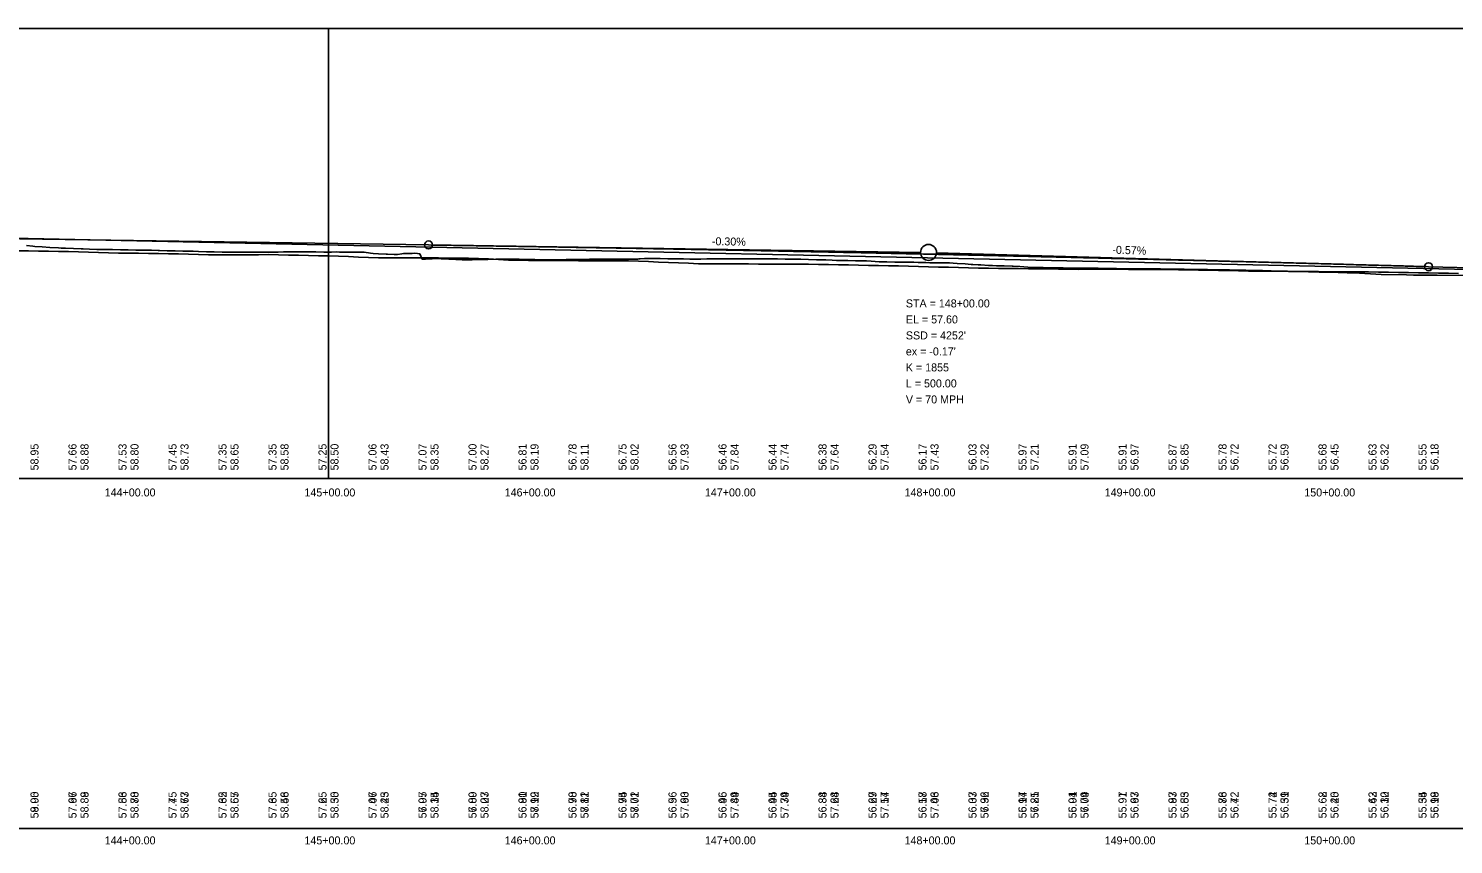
# Model space of a CAD drawing. Extents: x 3880794 to 3915434, y 287517 to 300173.
# Drawn here: x 3894888 to 3895601, y 297716 to 298124 of the extents above; entities that cross this region are included whole.
import ezdxf

# ---------------------------------------------------------------- set-up
doc = ezdxf.new("R2010")
doc.units = 0
for name, color, linetype in [('Level 1', 7, 'Continuous'), ('Level 2', 7, 'Continuous'), ('Level 30', 7, 'Continuous'), ('Level 31', 7, 'Continuous'), ('Level 32', 7, 'Continuous'), ('Level 62', 7, 'Continuous'), ('Level 63', 7, 'Continuous')]:
    doc.layers.add(name, color=color, linetype=linetype)

msp = doc.modelspace()

# ---------------------------------------------------------------- linework, layer by layer
at = {"layer": 'Level 1'}
for p, q in [((3894788.3, 298020.44), (3895088.3, 298015.94)), ((3895088.3, 298015.94), (3895334.3, 298012.25)), ((3895588.3, 298005.07), (3895342.3, 298012.08)), ((3895588.3, 298005.07), (3895939.87, 297995.06))]:
    msp.add_line(p, q, dxfattribs=at)
for points in [[(3894887.29, 298015.6), (3894890.4, 298015.3), (3894891.45, 298015.23), (3894895.11, 298014.97), (3894899.02, 298014.71), (3894903.22, 298014.44), (3894904.59, 298014.36), (3894906.85, 298014.26), (3894910.75, 298014.11), (3894914.67, 298013.98), (3894915.67, 298013.94), (3894918.85, 298013.79), (3894922.49, 298013.72), (3894926.4, 298013.66), (3894930.31, 298013.62), (3894934.23, 298013.59), (3894938.13, 298013.49), (3894942.04, 298013.41), (3894945.95, 298013.34), (3894948.52, 298013.31), (3894949.86, 298013.27), (3894953.14, 298013.2), (3894953.77, 298013.18), (3894957.69, 298013.07), (3894961.6, 298012.97), (3894965.51, 298012.89), (3894967.48, 298012.86), (3894969.42, 298012.8), (3894970.56, 298012.77), (3894973.33, 298012.67), (3894977.24, 298012.55), (3894981.15, 298012.44), (3894985.15, 298012.35), (3894988.97, 298012.31), (3894992.88, 298012.32), (3894996.79, 298012.35), (3895000.7, 298012.39), (3895004.62, 298012.38), (3895008.53, 298012.39), (3895012.44, 298012.41), (3895013.09, 298012.42), (3895015.82, 298012.46), (3895016.35, 298012.46), (3895020.26, 298012.45), (3895024.17, 298012.45), (3895028.08, 298012.47), (3895028.39, 298012.47), (3895029.75, 298012.46), (3895031.99, 298012.44), (3895035.9, 298012.42), (3895039.81, 298012.42), (3895042.29, 298012.43), (3895043.73, 298012.39), (3895047.63, 298012.35), (3895051.54, 298012.33), (3895055.46, 298012.33), (3895056.14, 298012.33), (3895059.37, 298011.85), (3895060.62, 298011.67), (3895063.28, 298011.57), (3895067.19, 298011.3), (3895067.85, 298011.26), (3895071.1, 298011.24), (3895072.76, 298011.23), (3895075.01, 298011.54), (3895075.77, 298011.64), (3895078.92, 298011.68), (3895080.16, 298011.69), (3895081.44, 298011.76), (3895082.83, 298011.61), (3895084.03, 298011.5), (3895085.11, 298008.85), (3895085.54, 298008.8), (3895086.06, 298008.85), (3895086.74, 298008.89), (3895088.52, 298008.97), (3895089.55, 298008.97)], [(3895089.55, 298008.97), (3895089.86, 298008.94), (3895090.18, 298009.03), (3895090.77, 298009.11), (3895094.56, 298008.95), (3895098.48, 298008.79), (3895102, 298008.65), (3895102.39, 298008.62), (3895105.06, 298008.48), (3895106.3, 298008.5), (3895110.21, 298008.58), (3895114.12, 298008.66), (3895118.03, 298008.74), (3895121.94, 298008.82), (3895124.48, 298008.86), (3895124.83, 298008.86), (3895125.85, 298008.88), (3895126.46, 298008.89), (3895127.21, 298008.88), (3895129.76, 298008.84), (3895133.67, 298008.78), (3895137.58, 298008.71), (3895141.49, 298008.64), (3895145.41, 298008.57), (3895149.31, 298008.5), (3895149.84, 298008.49), (3895150.46, 298008.52), (3895153.23, 298008.55), (3895157.14, 298008.61), (3895161.05, 298008.66), (3895164.96, 298008.71), (3895168.87, 298008.76), (3895170.82, 298008.77), (3895172.78, 298008.81), (3895174.14, 298008.84), (3895176.69, 298008.85), (3895180.6, 298008.85), (3895184.51, 298008.86), (3895188.42, 298008.87), (3895192.33, 298008.88), (3895192.96, 298008.88), (3895193.58, 298009.02), (3895194.16, 298009.04), (3895196.25, 298009.12), (3895198.15, 298009.2), (3895200.16, 298009.17), (3895204.07, 298009.12), (3895207.98, 298009.07), (3895211.89, 298009.02), (3895215.8, 298008.96), (3895219.02, 298008.91), (3895219.71, 298008.91), (3895223.62, 298008.92), (3895224.48, 298008.92), (3895227.53, 298008.93), (3895231.44, 298008.93), (3895235.35, 298008.93), (3895239.26, 298008.93), (3895242.09, 298008.93), (3895243.18, 298008.94), (3895247.09, 298008.97), (3895249.09, 298008.98), (3895251, 298008.98), (3895254.91, 298008.98), (3895258.82, 298008.98), (3895260.18, 298008.98), (3895262.73, 298008.95), (3895266.64, 298008.92), (3895269.11, 298008.9), (3895270.55, 298008.86), (3895274.46, 298008.77), (3895278.37, 298008.67), (3895282.28, 298008.57), (3895284.82, 298008.51), (3895286.19, 298008.47), (3895286.9, 298008.45), (3895290.1, 298008.3), (3895292.26, 298008.2), (3895294.02, 298008.18), (3895297.93, 298008.12), (3895301.84, 298008.07), (3895305.75, 298008.01), (3895307.28, 298007.99), (3895309.66, 298007.8), (3895313.57, 298007.5), (3895314.04, 298007.47), (3895314.57, 298007.46), (3895317.48, 298007.43), (3895321.39, 298007.39), (3895322.29, 298007.38), (3895325.3, 298007.35), (3895329.21, 298007.31), (3895330.96, 298007.29), (3895333.12, 298007.23), (3895337.04, 298007.11), (3895338.95, 298007.06), (3895340.01, 298007.02), (3895340.95, 298007.04), (3895341.51, 298007.05), (3895344.86, 298007), (3895348.77, 298006.94)], [(3895348.77, 298006.94), (3895350.58, 298006.91), (3895352.68, 298006.75), (3895356.59, 298006.45), (3895359.56, 298006.22), (3895360.5, 298006.17), (3895363.13, 298006.03), (3895364.41, 298005.96), (3895368.32, 298005.74), (3895370.36, 298005.63), (3895372.23, 298005.57), (3895376.19, 298005.44), (3895380.05, 298005.38), (3895380.63, 298005.38), (3895383.96, 298005.16), (3895387.88, 298004.92), (3895391.79, 298004.67), (3895392.42, 298004.63), (3895395.7, 298004.59), (3895399.61, 298004.53), (3895403.52, 298004.48), (3895405.56, 298004.45), (3895407.43, 298004.42), (3895411.34, 298004.39), (3895415.25, 298004.36), (3895419.45, 298004.33), (3895423.07, 298004.27), (3895426.98, 298004.2), (3895430.89, 298004.13), (3895431.87, 298004.11), (3895432.24, 298004.11), (3895434.81, 298004.07), (3895435.86, 298004.05), (3895438.72, 298004.05), (3895442.63, 298004.04), (3895446.54, 298004.03), (3895449.77, 298004.02), (3895450.45, 298004.02), (3895450.97, 298004.02), (3895454.36, 298003.97), (3895458.27, 298003.91), (3895460.23, 298003.88), (3895462.18, 298003.85), (3895466.09, 298003.8), (3895470, 298003.75), (3895473.91, 298003.7), (3895476.71, 298003.67), (3895477.82, 298003.65), (3895484.82, 298003.54), (3895486.85, 298003.52), (3895488.82, 298003.46), (3895505.33, 298003.09), (3895514.12, 298002.86), (3895517.76, 298002.78), (3895533.56, 298002.39), (3895543.07, 298002.15), (3895547.55, 298002.04), (3895551.18, 298001.98), (3895564.66, 298001.21), (3895577.36, 298001.05), (3895580.87, 298000.88), (3895592.62, 298000.86), (3895605.89, 298000.7)]]:
    msp.add_lwpolyline(points, dxfattribs=at)
msp.add_circle((3895338.3, 298012.19), 4, dxfattribs=at)
msp.add_spline([(3895088.3, 298015.94), (3895098.3, 298015.79), (3895108.3, 298015.64), (3895118.3, 298015.48), (3895128.3, 298015.32), (3895138.3, 298015.16), (3895148.3, 298014.99), (3895158.3, 298014.82), (3895168.3, 298014.65), (3895178.3, 298014.48), (3895188.3, 298014.31), (3895198.3, 298014.13), (3895208.3, 298013.95), (3895218.3, 298013.76), (3895228.3, 298013.58), (3895238.3, 298013.39), (3895248.3, 298013.2), (3895258.3, 298013), (3895268.3, 298012.8), (3895278.3, 298012.6), (3895288.3, 298012.4), (3895298.3, 298012.2), (3895308.3, 298011.99), (3895318.3, 298011.78), (3895328.3, 298011.56), (3895338.3, 298011.35), (3895348.3, 298011.13), (3895358.3, 298010.91), (3895368.3, 298010.68), (3895378.3, 298010.46), (3895388.3, 298010.23), (3895398.3, 298009.99), (3895408.3, 298009.76), (3895418.3, 298009.52), (3895428.3, 298009.28), (3895438.3, 298009.04), (3895448.3, 298008.79), (3895458.3, 298008.54), (3895468.3, 298008.29), (3895478.3, 298008.04), (3895488.3, 298007.78), (3895498.3, 298007.53), (3895508.3, 298007.26), (3895518.3, 298007), (3895528.3, 298006.73), (3895538.3, 298006.46), (3895548.3, 298006.19), (3895558.3, 298005.91), (3895568.3, 298005.64), (3895578.3, 298005.35), (3895588.3, 298005.07)], degree=3, dxfattribs=at)
at = {"layer": 'Level 2'}
msp.add_line((3894788.3, 298021.32), (3895938.3, 297996.62), dxfattribs=at)
for points in [[(3894883.3, 298013.04), (3894888.3, 298012.98), (3894893.3, 298012.91), (3894898.3, 298012.83), (3894903.3, 298012.74), (3894908.3, 298012.61), (3894913.3, 298012.49), (3894918.3, 298012.34), (3894923.3, 298012.18), (3894928.3, 298012.02), (3894933.3, 298011.89), (3894938.3, 298011.85), (3894943.3, 298011.78), (3894948.3, 298011.71), (3894953.3, 298011.63), (3894958.3, 298011.57), (3894963.3, 298011.46), (3894968.3, 298011.32), (3894973.3, 298011.17), (3894978.3, 298011.03), (3894983.3, 298010.99), (3894988.3, 298010.96), (3894993.3, 298011), (3894998.3, 298011.04), (3895003.3, 298011.08), (3895008.3, 298011.11), (3895013.3, 298010.96), (3895018.3, 298010.87), (3895023.3, 298010.78), (3895028.3, 298010.68), (3895033.3, 298010.59), (3895038.3, 298010.44)], [(3895038.3, 298010.44), (3895043.3, 298010.29), (3895048.3, 298010.1), (3895053.3, 298009.9), (3895058.3, 298009.7), (3895063.3, 298009.51), (3895068.3, 298009.46), (3895073.3, 298009.49), (3895078.3, 298009.52), (3895083.3, 298009.54), (3895088.3, 298009.52), (3895093.3, 298009.47), (3895098.3, 298009.4), (3895103.3, 298009.33), (3895108.3, 298009.26), (3895113.3, 298009.2), (3895118.3, 298008.94), (3895123.3, 298008.68), (3895128.3, 298008.42), (3895133.3, 298008.26), (3895138.3, 298008.23), (3895143.3, 298008.2), (3895148.3, 298008.15), (3895153.3, 298008.11), (3895158.3, 298008.1), (3895163.3, 298008.08), (3895168.3, 298008.05), (3895173.3, 298007.95), (3895178.3, 298007.95), (3895183.3, 298007.95), (3895188.3, 298007.96), (3895193.3, 298007.8), (3895198.3, 298007.59), (3895203.3, 298007.37), (3895208.3, 298007.16), (3895213.3, 298006.98), (3895218.3, 298006.84), (3895223.3, 298006.45), (3895228.3, 298006.45), (3895233.3, 298006.46), (3895238.3, 298006.47), (3895243.3, 298006.47), (3895248.3, 298006.46), (3895253.3, 298006.41), (3895258.3, 298006.41), (3895263.3, 298006.4), (3895268.3, 298006.39), (3895273.3, 298006.35), (3895278.3, 298006.27), (3895283.3, 298006.19), (3895288.3, 298006.1), (3895293.3, 298006.02), (3895298.3, 298005.95), (3895303.3, 298005.85), (3895308.3, 298005.75), (3895313.3, 298005.65), (3895318.3, 298005.52), (3895323.3, 298005.47), (3895328.3, 298005.33), (3895333.3, 298005.2), (3895338.3, 298005.06), (3895343.3, 298004.92), (3895348.3, 298004.77), (3895353.3, 298004.62), (3895358.3, 298004.47), (3895363.3, 298004.35), (3895368.3, 298004.3), (3895373.3, 298004.25), (3895378.3, 298004.2), (3895383.3, 298004.15), (3895388.3, 298004.05), (3895393.3, 298004), (3895398.3, 298003.93), (3895403.3, 298003.86), (3895408.3, 298003.79), (3895413.3, 298003.74), (3895418.3, 298003.77), (3895423.3, 298003.78), (3895428.3, 298003.8), (3895433.3, 298003.81), (3895438.3, 298003.73), (3895443.3, 298003.74), (3895448.3, 298003.75), (3895453.3, 298003.75), (3895458.3, 298003.61), (3895463.3, 298003.53), (3895468.3, 298003.44), (3895473.3, 298003.36), (3895478.3, 298003.27), (3895483.3, 298003.21), (3895488.3, 298003.11), (3895493.3, 298003.02), (3895498.3, 298002.92), (3895503.3, 298002.85), (3895508.3, 298002.82), (3895513.3, 298002.78), (3895518.3, 298002.74), (3895523.3, 298002.7), (3895528.3, 298002.66), (3895533.3, 298002.62), (3895538.3, 298002.58)], [(3895538.3, 298002.58), (3895543.3, 298002.54), (3895548.3, 298002.51), (3895553.3, 298002.47), (3895558.3, 298002.43), (3895563.3, 298002.35), (3895568.3, 298002.27), (3895573.3, 298002.19), (3895578.3, 298002.11), (3895583.3, 298002.02), (3895588.3, 298001.93), (3895593.3, 298001.85), (3895598.3, 298001.77), (3895603.3, 298001.69)]]:
    msp.add_lwpolyline(points, dxfattribs=at)
at = {"layer": 'Level 31'}
for centre in [(3895088.3, 298015.94), (3895588.3, 298005.07)]:
    msp.add_circle(centre, 2, dxfattribs=at)
at = {"layer": 'Level 62'}
for points in [[(3894338.3, 297899.19), (3895038.3, 297899.19), (3895038.3, 298124.19), (3894338.3, 298124.19)], [(3894338.3, 297899.19), (3895038.3, 297899.19), (3895038.3, 298124.19), (3894338.3, 298124.19)], [(3895038.3, 297899.19), (3895738.3, 297899.19), (3895738.3, 298124.19), (3895038.3, 298124.19)], [(3895038.3, 297899.19), (3895738.3, 297899.19), (3895738.3, 298124.19), (3895038.3, 298124.19)]]:
    msp.add_lwpolyline(points, close=True, dxfattribs=at)
at = {"layer": 'Level 63'}
msp.add_line((3881538.3, 297724.19), (3896411.35, 297724.19), dxfattribs=at)

# ---------------------------------------------------------------- texts
at = {"layer": 'Level 30'}
for s, p in [('144+00.00', (3894926.39, 297890.19)), ('144+00.00', (3894926.39, 297890.19)), ('145+00.00', (3895026.27, 297890.19)), ('145+00.00', (3895026.27, 297890.19)), ('146+00.00', (3895126.39, 297890.19)), ('146+00.00', (3895126.39, 297890.19)), ('147+00.00', (3895226.49, 297890.19)), ('147+00.00', (3895226.49, 297890.19)), ('148+00.00', (3895326.33, 297890.19)), ('148+00.00', (3895326.33, 297890.19)), ('149+00.00', (3895426.39, 297890.19)), ('149+00.00', (3895426.39, 297890.19)), ('150+00.00', (3895526.2, 297890.19)), ('150+00.00', (3895526.2, 297890.19)), ('144+00.00', (3894926.39, 297716.19)), ('144+00.00', (3894926.39, 297716.19)), ('145+00.00', (3895026.27, 297716.19)), ('145+00.00', (3895026.27, 297716.19)), ('146+00.00', (3895126.39, 297716.19)), ('146+00.00', (3895126.39, 297716.19)), ('147+00.00', (3895226.49, 297716.19)), ('147+00.00', (3895226.49, 297716.19)), ('148+00.00', (3895326.33, 297716.19)), ('148+00.00', (3895326.33, 297716.19)), ('149+00.00', (3895426.39, 297716.19)), ('149+00.00', (3895426.39, 297716.19)), ('150+00.00', (3895526.2, 297716.19)), ('150+00.00', (3895526.2, 297716.19))]:
    msp.add_text(s, height=4, dxfattribs=at).set_placement(p)
at = {"layer": 'Level 31'}
for s, rotation, p in [('-0.30%', 359.14063, (3895229.96, 298015.82)), ('-0.57%', 358.3687, (3895430.19, 298011.58)), ('58.95', 90, (3894893.3, 297903.19)), ('58.88', 90, (3894918.3, 297903.19)), ('58.80', 90, (3894943.3, 297903.19)), ('58.73', 90, (3894968.3, 297903.19)), ('58.65', 90, (3894993.3, 297903.19)), ('58.58', 90, (3895018.3, 297903.19)), ('58.50', 90, (3895043.3, 297903.19)), ('58.43', 90, (3895068.3, 297903.19)), ('58.35', 90, (3895093.3, 297903.19)), ('58.27', 90, (3895118.3, 297903.19)), ('58.19', 90, (3895143.3, 297903.19)), ('58.11', 90, (3895168.3, 297903.19)), ('58.02', 90, (3895193.3, 297903.19)), ('57.93', 90, (3895218.3, 297903.19)), ('57.84', 90, (3895243.3, 297903.19)), ('57.74', 90, (3895268.3, 297903.19)), ('57.64', 90, (3895293.3, 297903.19)), ('57.54', 90, (3895318.3, 297903.19)), ('57.43', 90, (3895343.3, 297903.19)), ('57.32', 90, (3895368.3, 297903.19)), ('57.21', 90, (3895393.3, 297903.19)), ('57.09', 90, (3895418.3, 297903.19)), ('56.97', 90, (3895443.3, 297903.19)), ('56.85', 90, (3895468.3, 297903.19)), ('56.72', 90, (3895493.3, 297903.19)), ('56.59', 90, (3895518.3, 297903.19)), ('56.45', 90, (3895543.3, 297903.19)), ('56.32', 90, (3895568.3, 297903.19)), ('56.18', 90, (3895593.3, 297903.19)), ('58.95', 90, (3894893.3, 297729.19)), ('57.97', 90, (3894912.3, 297729.19)), ('58.88', 90, (3894918.3, 297729.19)), ('57.86', 90, (3894937.3, 297729.19)), ('58.80', 90, (3894943.3, 297729.19)), ('57.75', 90, (3894962.3, 297729.19)), ('58.73', 90, (3894968.3, 297729.19)), ('57.62', 90, (3894987.3, 297729.19)), ('58.65', 90, (3894993.3, 297729.19)), ('57.65', 90, (3895012.3, 297729.19)), ('58.58', 90, (3895018.3, 297729.19)), ('57.65', 90, (3895037.3, 297729.19)), ('58.50', 90, (3895043.3, 297729.19)), ('57.47', 90, (3895062.3, 297729.19)), ('58.43', 90, (3895068.3, 297729.19)), ('56.95', 90, (3895087.3, 297729.19)), ('58.35', 90, (3895093.3, 297729.19)), ('56.89', 90, (3895112.3, 297729.19)), ('58.27', 90, (3895118.3, 297729.19)), ('56.90', 90, (3895137.3, 297729.19)), ('58.19', 90, (3895143.3, 297729.19)), ('56.90', 90, (3895162.3, 297729.19)), ('58.11', 90, (3895168.3, 297729.19)), ('56.94', 90, (3895187.3, 297729.19)), ('58.02', 90, (3895193.3, 297729.19)), ('56.96', 90, (3895212.3, 297729.19)), ('57.93', 90, (3895218.3, 297729.19)), ('56.95', 90, (3895237.3, 297729.19)), ('57.84', 90, (3895243.3, 297729.19)), ('56.95', 90, (3895262.3, 297729.19)), ('57.74', 90, (3895268.3, 297729.19)), ('56.84', 90, (3895287.3, 297729.19)), ('57.64', 90, (3895293.3, 297729.19)), ('56.67', 90, (3895312.3, 297729.19)), ('57.54', 90, (3895318.3, 297729.19)), ('56.58', 90, (3895337.3, 297729.19)), ('57.43', 90, (3895343.3, 297729.19)), ('56.37', 90, (3895362.3, 297729.19)), ('57.32', 90, (3895368.3, 297729.19)), ('56.14', 90, (3895387.3, 297729.19)), ('57.21', 90, (3895393.3, 297729.19)), ('56.04', 90, (3895412.3, 297729.19)), ('57.09', 90, (3895418.3, 297729.19)), ('55.97', 90, (3895437.3, 297729.19)), ('56.97', 90, (3895443.3, 297729.19)), ('55.93', 90, (3895462.3, 297729.19)), ('56.85', 90, (3895468.3, 297729.19)), ('55.86', 90, (3895487.3, 297729.19)), ('56.72', 90, (3895493.3, 297729.19)), ('55.74', 90, (3895512.3, 297729.19)), ('56.59', 90, (3895518.3, 297729.19)), ('55.62', 90, (3895537.3, 297729.19)), ('56.45', 90, (3895543.3, 297729.19)), ('55.42', 90, (3895562.3, 297729.19)), ('56.32', 90, (3895568.3, 297729.19)), ('55.34', 90, (3895587.3, 297729.19)), ('56.18', 90, (3895593.3, 297729.19))]:
    msp.add_text(s, height=4, rotation=rotation, dxfattribs=at).set_placement(p)
for s, p in [('STA = 148+00.00', (3895326.98, 297984.71)), ('EL = 57.60', (3895326.98, 297976.71)), ("SSD = 4252'", (3895326.98, 297968.71)), ("ex = -0.17'", (3895326.98, 297960.71)), ('K = 1855', (3895326.98, 297952.71)), ('L = 500.00', (3895326.98, 297944.71)), ('V = 70 MPH', (3895326.98, 297936.71))]:
    msp.add_text(s, height=4, dxfattribs=at).set_placement(p)
at = {"layer": 'Level 32'}
for s, p in [('57.66', (3894912.3, 297903.19)), ('57.53', (3894937.3, 297903.19)), ('57.45', (3894962.3, 297903.19)), ('57.35', (3894987.3, 297903.19)), ('57.35', (3895012.3, 297903.19)), ('57.25', (3895037.3, 297903.19)), ('57.06', (3895062.3, 297903.19)), ('57.07', (3895087.3, 297903.19)), ('57.00', (3895112.3, 297903.19)), ('56.81', (3895137.3, 297903.19)), ('56.78', (3895162.3, 297903.19)), ('56.75', (3895187.3, 297903.19)), ('56.56', (3895212.3, 297903.19)), ('56.46', (3895237.3, 297903.19)), ('56.44', (3895262.3, 297903.19)), ('56.38', (3895287.3, 297903.19)), ('56.29', (3895312.3, 297903.19)), ('56.17', (3895337.3, 297903.19)), ('56.03', (3895362.3, 297903.19)), ('55.97', (3895387.3, 297903.19)), ('55.91', (3895412.3, 297903.19)), ('55.91', (3895437.3, 297903.19)), ('55.87', (3895462.3, 297903.19)), ('55.78', (3895487.3, 297903.19)), ('55.72', (3895512.3, 297903.19)), ('55.68', (3895537.3, 297903.19)), ('55.63', (3895562.3, 297903.19)), ('55.55', (3895587.3, 297903.19)), ('59.00', (3894893.3, 297729.19)), ('57.66', (3894912.3, 297729.19)), ('58.89', (3894918.3, 297729.19)), ('57.53', (3894937.3, 297729.19)), ('58.78', (3894943.3, 297729.19)), ('57.45', (3894962.3, 297729.19)), ('58.67', (3894968.3, 297729.19)), ('57.35', (3894987.3, 297729.19)), ('58.57', (3894993.3, 297729.19)), ('57.35', (3895012.3, 297729.19)), ('58.46', (3895018.3, 297729.19)), ('57.25', (3895037.3, 297729.19)), ('58.35', (3895043.3, 297729.19)), ('57.06', (3895062.3, 297729.19)), ('58.25', (3895068.3, 297729.19)), ('57.07', (3895087.3, 297729.19)), ('58.14', (3895093.3, 297729.19)), ('57.00', (3895112.3, 297729.19)), ('58.03', (3895118.3, 297729.19)), ('56.81', (3895137.3, 297729.19)), ('57.92', (3895143.3, 297729.19)), ('56.78', (3895162.3, 297729.19)), ('57.82', (3895168.3, 297729.19)), ('56.75', (3895187.3, 297729.19)), ('57.71', (3895193.3, 297729.19)), ('56.56', (3895212.3, 297729.19)), ('57.60', (3895218.3, 297729.19)), ('56.46', (3895237.3, 297729.19)), ('57.49', (3895243.3, 297729.19)), ('56.44', (3895262.3, 297729.19)), ('57.39', (3895268.3, 297729.19)), ('56.38', (3895287.3, 297729.19)), ('57.28', (3895293.3, 297729.19)), ('56.29', (3895312.3, 297729.19)), ('57.17', (3895318.3, 297729.19)), ('56.17', (3895337.3, 297729.19)), ('57.06', (3895343.3, 297729.19)), ('56.03', (3895362.3, 297729.19)), ('56.96', (3895368.3, 297729.19)), ('55.97', (3895387.3, 297729.19)), ('56.85', (3895393.3, 297729.19)), ('55.91', (3895412.3, 297729.19)), ('56.74', (3895418.3, 297729.19)), ('55.91', (3895437.3, 297729.19)), ('56.63', (3895443.3, 297729.19)), ('55.87', (3895462.3, 297729.19)), ('56.53', (3895468.3, 297729.19)), ('55.78', (3895487.3, 297729.19)), ('56.42', (3895493.3, 297729.19)), ('55.72', (3895512.3, 297729.19)), ('56.31', (3895518.3, 297729.19)), ('55.68', (3895537.3, 297729.19)), ('56.20', (3895543.3, 297729.19)), ('55.63', (3895562.3, 297729.19)), ('56.10', (3895568.3, 297729.19)), ('55.55', (3895587.3, 297729.19)), ('55.99', (3895593.3, 297729.19))]:
    msp.add_text(s, height=4, rotation=90, dxfattribs=at).set_placement(p)

doc.saveas('drawing.dxf')
